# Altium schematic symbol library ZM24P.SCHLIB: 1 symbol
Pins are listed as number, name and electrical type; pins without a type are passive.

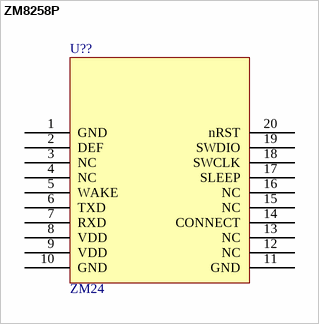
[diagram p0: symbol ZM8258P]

## ZM8258P
designator U??, comment ZM24
ZM8258P S0.02; 物料代码: 78.04.00264; 名称: 蓝牙模块; 厂商: ZHIYUAN; 贴片和直插: SMT; PCB备注: 231123FHX; 生产单位: PCS
footprint ZM8258P
pins: 1 GND, 2 DEF, 3 NC, 4 NC, 5 WAKE, 6 TXD, 7 RXD, 8 VDD, 9 VDD, 10 GND, 11 GND, 12 NC, 13 NC, 14 CONNECT, 15 NC, 16 NC, 17 SLEEP, 18 SWCLK, 19 SWDIO, 20 nRST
